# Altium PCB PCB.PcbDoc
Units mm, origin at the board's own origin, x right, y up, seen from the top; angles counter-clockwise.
Board outline 35 x 11 mm, 4 copper layers (TOP, GND, SIG, BOTTOM), stack 1.586 mm thick; 54 components, 35 nets, 188 pads, 91 vias.
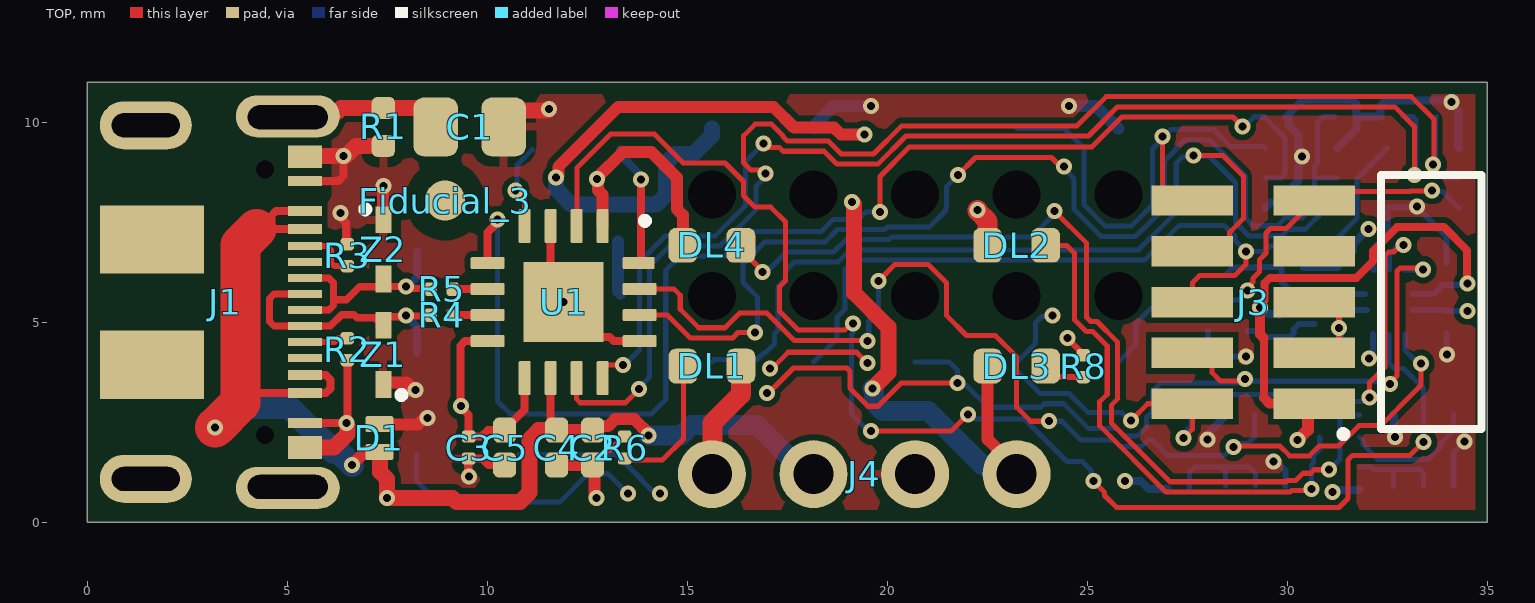
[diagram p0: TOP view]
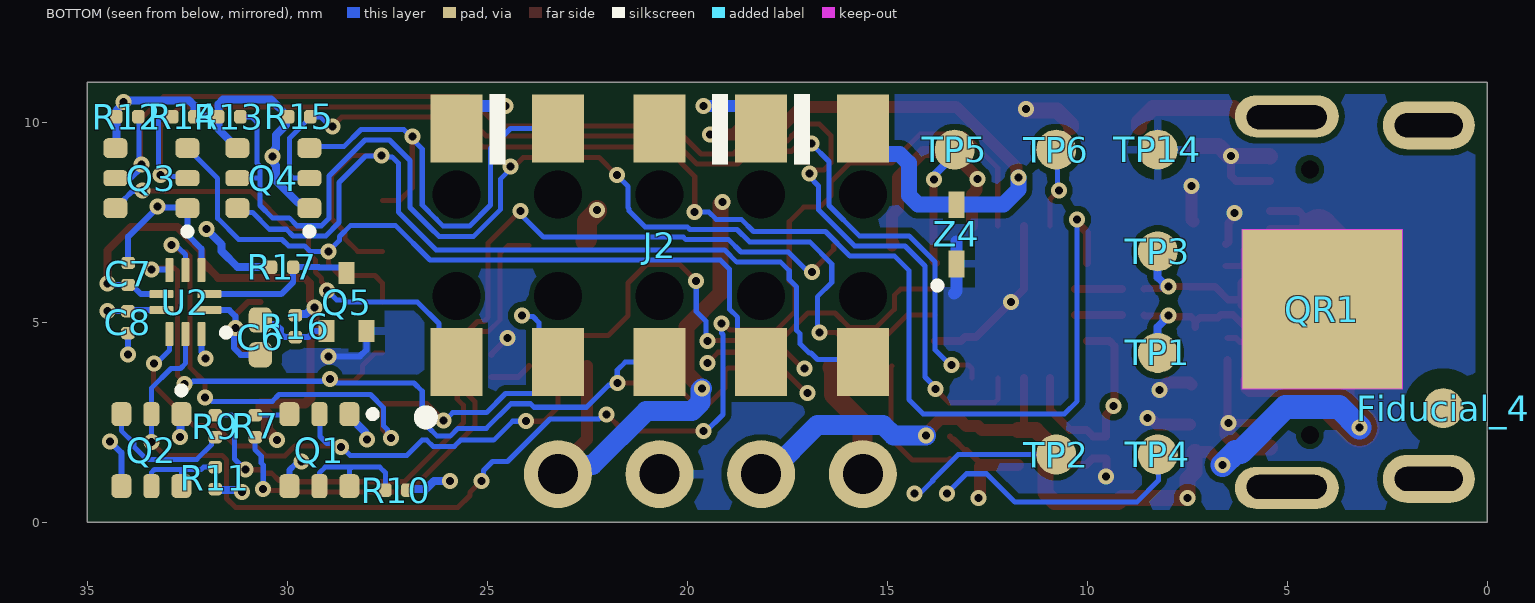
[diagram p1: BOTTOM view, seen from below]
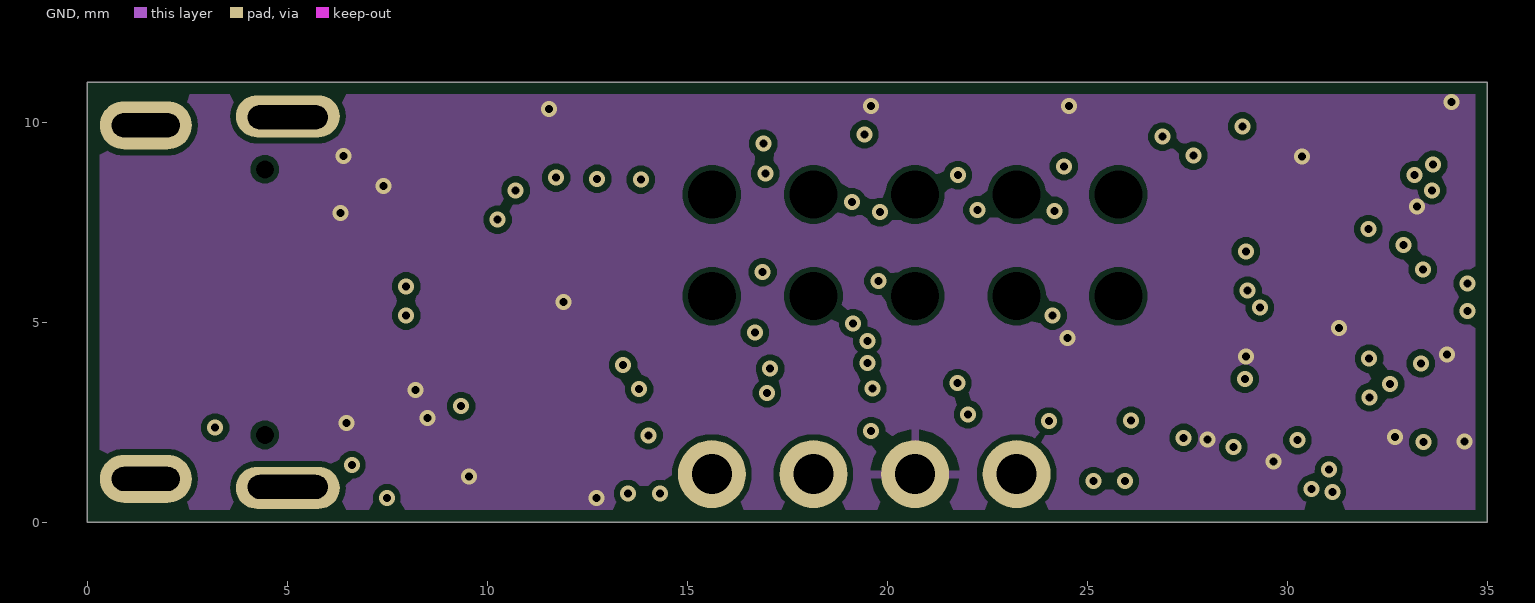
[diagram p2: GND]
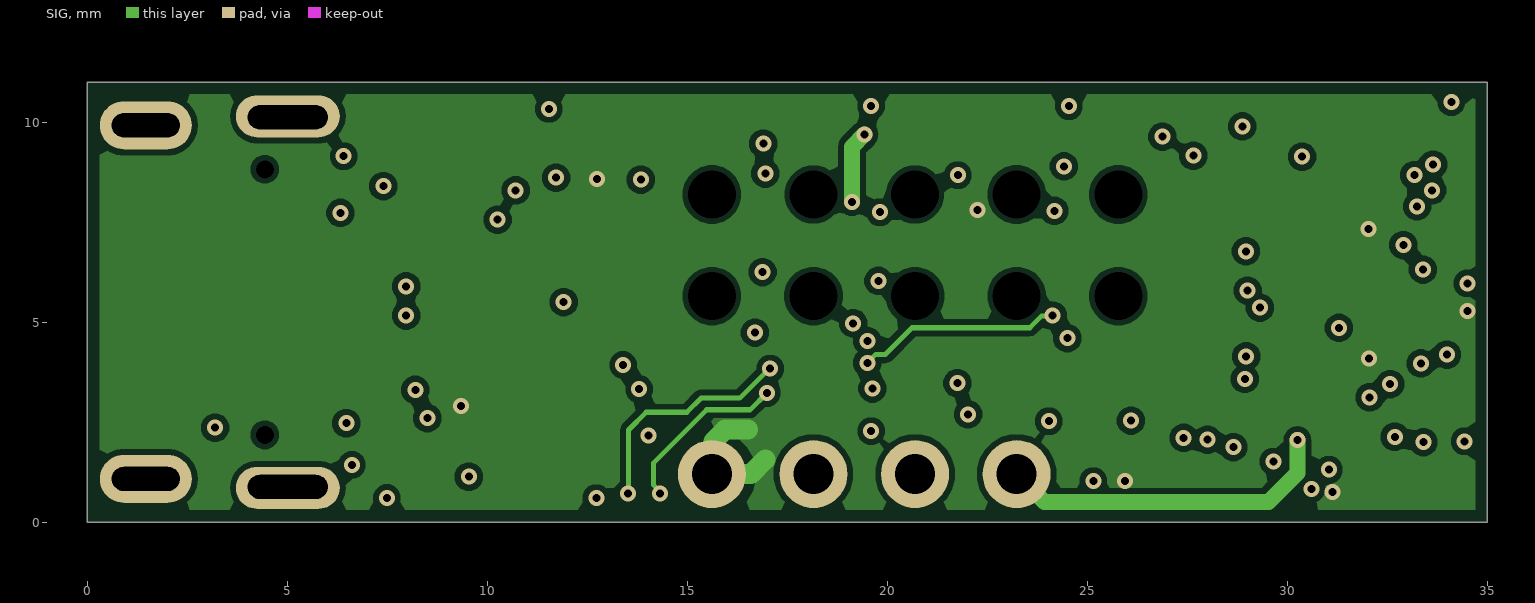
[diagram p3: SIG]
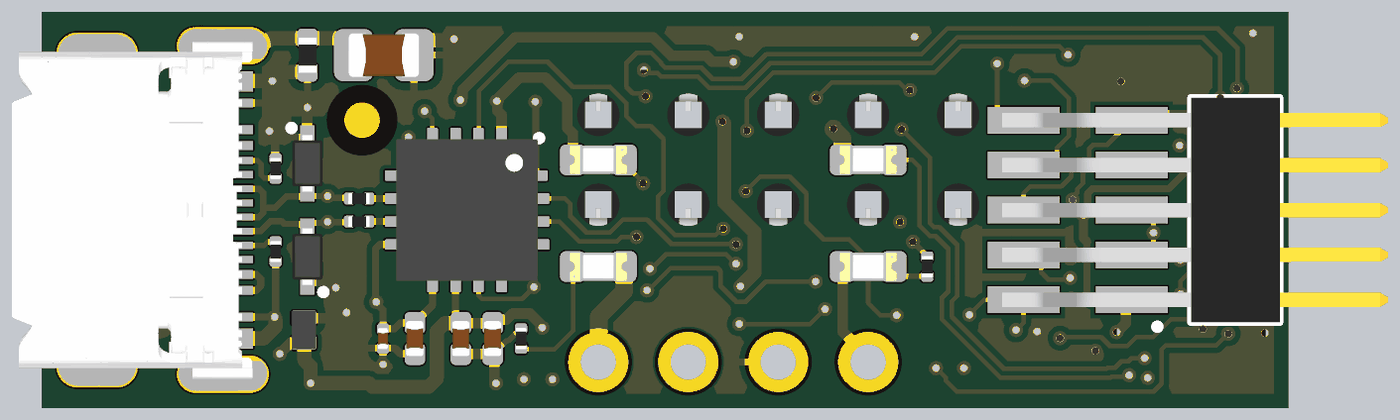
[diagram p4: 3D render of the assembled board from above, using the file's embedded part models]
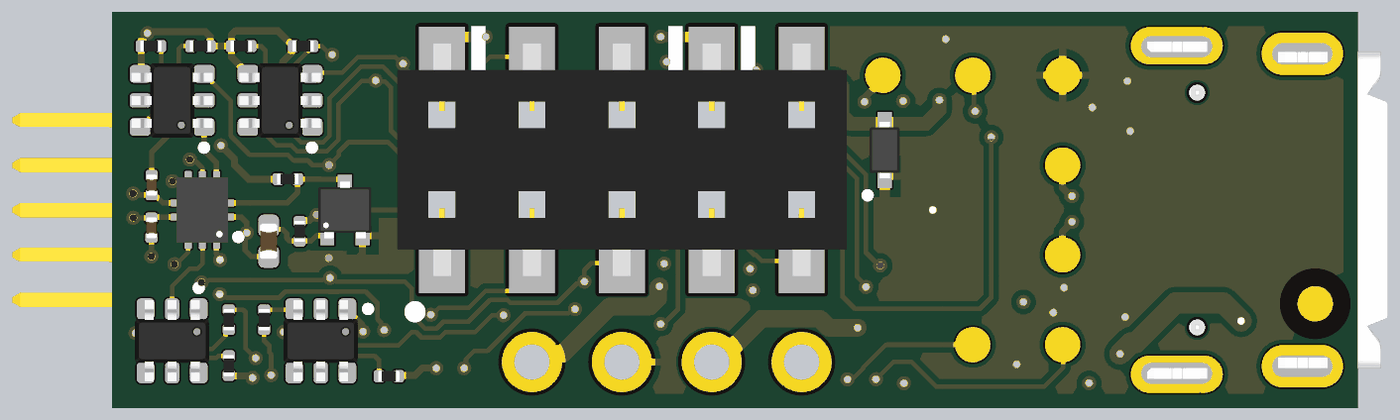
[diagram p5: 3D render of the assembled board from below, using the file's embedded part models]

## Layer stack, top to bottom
Top Solder: solder mask 0.0102, Solder Resist, Dk 3.5
TOP: signal copper 0.018
Dielectric 1: prepreg 0.14, PP-014, Dk 4.2
GND: signal copper 0.035
Dielectric2: core 1.2, FR-4, Dk 4.8
SIG: signal copper 0.035
Dielectric3: prepreg 0.14, PP-014, Dk 4.2
BOTTOM: signal copper 0.018
Bottom Solder: solder mask 0.0102, Solder Resist, Dk 3.5

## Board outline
0,0 35,0 35,11 0,11

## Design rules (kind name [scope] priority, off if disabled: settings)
BoardOutlineClearance Mousebites [(ObjectKind = 'Pad') And (Name = 'Free-MOUSEBITE')] p1: gap=0 ignorepadtopadclearanceinfootprint=FALSE
BoardOutlineClearance Silks [(OnLayer('Top Overlay') OR OnLayer('Bottom Overlay'))] p2: gap=0 ignorepadtopadclearanceinfootprint=FALSE
BoardOutlineClearance [All] p3: gap=0.3 ignorepadtopadclearanceinfootprint=FALSE
Clearance COPPER_0.15mm [All] p1: gap=0.127 ignorepadtopadclearanceinfootprint=FALSE except(0.15: Arc-Fill Arc-Poly Arc-Region Track-Fill Track-Poly Track-Region SMDPad-Fill SMDPad-Poly SMDPad-Region THPad-Fill THPad-Poly THPad-Region Via-Fill Via-Poly Via-Region Fill-Fill Fill-Poly Fill-Region Poly-Poly Poly-Region Region-Region)
Clearance "Generic clearance 0.127mm" [All] p2: gap=0.127 ignorepadtopadclearanceinfootprint=FALSE
ComponentClearance [All] p1: gap=0.2 collisioncheckmode=3 verticalgap=0 showdistances=TRUE
DiffPairsRouting USB [InDifferentialPairClass('USB')] p1: maxlimit=0.24 minlimit=0.127 mostfreqgap=0.24 toplayer_maxgap=0.127 toplayer_prefgap=0.127 toplayer_minwidth=0.18 toplayer_maxwidth=0.18 toplayer_prefwidth=0.18 midlayer2_mingap=0.24 midlayer2_minwidth=0.15 midlayer2_maxwidth=0.15 midlayer2_prefwidth=0.15 bottomlayer_maxgap=0.127 bottomlayer_prefgap=0.127 bottomlayer_minwidth=0.18 bottomlayer_maxwidth=0.18 bottomlayer_prefwidth=0.18 impedanceprofiledriven=TRUE impedanceprofileid={017A1981-E7F6-45B4-9447-017FE77E18B0} impedanceprofilevalue=90.000000 maxuncoupledlength=12.7
Height [All] p1: minheight=0 maxheight=30 prefheight=12.7
HoleSize [All] p1: absolutevalues=TRUE maxlimit=30 minlimit=0.1 maxpercent=80.000 minpercent=20.000
HoleToHoleClearance [All] p1: gap=0.25 allowstackedmicrovias=FALSE
MatchedLengths MatchedLengths_USB [InDifferentialPair('USB_D_1')] p1: tolerance=3.81 checknetsindiffpair=FALSE checkdiffpairvsdiffpair=TRUE checkxsignals=TRUE checkothers=TRUE
MinimumAnnularRing [All] p1: minimumring=0.09
PlaneConnect [All] p1: pad.planeconnectstyle=Relief pad.reliefexpansion=0.508 pad.reliefentries=4 pad.reliefconductorwidth=0.254 pad.reliefairgap=0.254 via.planeconnectstyle=Direct via.reliefexpansion=0.508 via.reliefentries=4 via.reliefconductorwidth=0.254 via.reliefairgap=0.254
PolygonConnect QR_polygon [(ObjectKind = 'Pad') And (Component = 'QR1') And (AsMM(PadXSize_AllLayers) = 4) And (AsMM(PadYSize_AllLayers) = 4)] p1: connectstyle=Direct reliefconductorwidth=0.254 reliefentries=4 polygonreliefangle="90 Angle" airgapwidth=0.254
PolygonConnect [All] p2: thpad.connectstyle=Relief thpad.reliefconductorwidth=0.2 thpad.reliefentries=4 thpad.polygonreliefangle="90 Angle" thpad.airgapwidth=0.254 smdpad.connectstyle=Relief smdpad.reliefconductorwidth=0.2 smdpad.reliefentries=4 smdpad.polygonreliefangle="90 Angle" smdpad.airgapwidth=0.254 via.connectstyle=Direct via.reliefconductorwidth=0.254 via.reliefentries=4 via.polygonreliefangle="90 Angle" via.airgapwidth=0.254
RoomDefinition TOP [InComponentClass('TOP')] p1: confinementstyle=ConfineIn formatcopy=TRUE lockcomponents=FALSE outline 77.708,-9.444 105.708,-9.444 105.708,-1.444 77.708,-1.444
RoutingVias StandardVias [All] p1: holewidth=0.2 width=0.4 viastyle="Through Hole" minholewidth=0.1 minwidth=0.2 maxholewidth=0.3 maxwidth=0.6
SMDToCorner [All] p1: distance=39370
SilkToSilkClearance [All] p1: silktosilkclearance=0.2
SilkToSolderMaskClearance [IsPad] p1: minsilkscreentomaskgap=0.15 clearancetoexposedcopper=TRUE
SolderMaskExpansion VIAtented [IsVia] p1: expansion=0.102 istentingtop=TRUE
SolderMaskExpansion [All] p2: expansion=0.05 istentingtop=FALSE
SupplyNets "Schematic Supply Nets_3" [InNet('+5V')] p1: voltage=0.000
SupplyNets "Schematic Supply Nets_2" [InNet('+3V3')] p2: voltage=0.000
SupplyNets "Schematic Supply Nets_1" [InNet('VTARGET')] p3: voltage=0.000
SupplyNets "Schematic Supply Nets" [InNet('GND')] p4: voltage=0.000
UnConnectedPin [All] p1:
UnRoutedNet [All] p1: checkbadconnections=TRUE
ViasUnderSMD [All] p1: allowed=FALSE
Width StandardTraces [All] p1: maxlimit=5 minlimit=0.127 preferedwidth=0.15 toplayer_prefwidth=0.127 bottomlayer_prefwidth=0.127 minimp=50.000000 maximp=50.000000 favimp=50.000000
21 further rules are at their usual default settings.

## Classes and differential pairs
differential pair class USB: USB_D_1
differential pair USB_D_1: +USB_D_1_P -USB_D_1_N

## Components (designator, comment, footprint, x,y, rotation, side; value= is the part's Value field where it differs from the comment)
C1 "FV21X472K102ECG" CAP-0805 9.558,9.88 r180 top value=4.7nF
C2 "C1005B103K500NT" CAP-0402 12.633,1.865 r90 top value=10nF
C3 "CL03A104KP3NNNC" CAP-0201 9.533,1.865 r90 top value=100nF
C4 "C1005A475M6R3NT" CAP-0402 11.733,1.865 r90 top value=4.7µF
C5 "C1005A475M6R3NT" CAP-0402 10.433,1.865 r90 top value=4.7µF
C6 "C1005A475M6R3NT" CAP-0402 30.675,4.618 r90 bottom value=4.7µF
C7 "CL03A104KP3NNNC" CAP-0201 33.979,6.204 r270 bottom value=100nF
C8 "CL03A104KP3NNNC" CAP-0201 33.985,5 r90 bottom value=100nF
D1 "STN101050B301" X1-DFN1006-2 7.3,2.1 r270 top
DL1 "LTST-C190KGKT" LEDC1608X80N-AK 15.614,3.9 r0 top
DL2 "LTST-C190KSKT" LEDC1608X80N-AK 23.234,6.92 r180 top
DL3 "XHY-STB0603SR" LEDC1608X80N-AK 23.234,3.9 r180 top
DL4 "LTST-C190KSKT" LEDC1608X80N-AK 15.614,6.92 r180 top
Fiducial_3 "Fiducial mark 1mm with 2mm solder" "Fiducial mark 1mm with circle-Footprint-1" 8.943,8.04 r90 top
Fiducial_4 "Fiducial mark 1mm with 2mm solder" "Fiducial mark 1mm with circle-Footprint-1" 1.1,2.848 r90 bottom
J1 "CX90B-16P" CX90B-16P-Footprint-1 3.45,5.5 r270 top locked
J2 "HLE-105-02-L-DV-K-TR" HLE-105-02-L-DV-BE-K-TR 20.694,6.92 r90 bottom locked
J3 "FTSH-105-01-L-DH-C-TR" FTSH-105-01-L-DH-C-TR 29.15,5.5 r270 top locked
J4 "HEADER TH 2.54mm VERT. 1x004POS" "PIN HEADER 2.54mm VERT. 1x4POS-Footprint-1" 19.424,1.2 r180 top locked
Q1 "2N7002DW-7-F" SOT363 29.2,1.8 r0 bottom
Q2 "2N7002DW-7-F" SOT363 33.4,1.8 r0 bottom
Q3 "2N7002DW-7-F" SOT363 33.4,8.6 r90 bottom
Q4 "2N7002DW-7-F" SOT363 30.35,8.6 r90 bottom
Q5 "PJE138K_R1_00001" SOT-523 28.52,5.5 r90 bottom
QR1 "QR CODE 4x4mm" "QR CODE 4x4mm" 4.129,5.324 r0 bottom
R1 "CRCW04021M00FKED" RES-0402 7.4,9.88 r90 top value=1M
R2 "RC0201FR-075K1L" RES-0201 6.5,4.325 r90 top value=5.1k
R3 "RC0201FR-075K1L" RES-0201 6.5,6.675 r270 top value=5.1k
R4 "CRCW020127R0FNED" RES-0201 8.858,5.175 r180 top value=27
R5 "CRCW020127R0FNED" RES-0201 8.858,5.825 r180 top value=27
R6 "RC0201FR-071KL" RES-0201 13.433,1.865 r270 top value=1k
R7 "AC0201FR-07330RL" RES-0201 30.8,2.4 r270 bottom value=330
R8 "AC0201FR-07330RL" RES-0201 24.9,3.9 r270 top value=330
R9 "AC0201FR-07330RL" RES-0201 31.8,2.4 r90 bottom value=330
R10 "RC0201FR-075K1L" RES-0201 27.275,0.8 r180 bottom value=5.1k
R11 "RC0201FR-075K1L" RES-0201 31.8,1.1 r270 bottom value=5.1k
R12 "RC0201FR-075K1L" RES-0201 34,10.135 r180 bottom value=5.1k
R13 "RC0201FR-075K1L" RES-0201 31.45,10.135 r180 bottom value=5.1k
R14 "RC0201FR-075K1L" RES-0201 32.6,10.135 r0 bottom value=5.1k
R15 "RC0201FR-075K1L" RES-0201 29.7,10.135 r180 bottom value=5.1k
R16 "RC0201FR-075K1L" RES-0201 29.798,4.898 r90 bottom value=5.1k
R17 "RC0201FR-075K1L" RES-0201 30.131,6.374 r180 bottom value=5.1k
TP1 "Test point 1.00mm" TP-1.00MM 8.238,4.23 r0 bottom
TP2 "Test point 1.00mm" TP-1.00MM 10.778,1.69 r90 bottom
TP3 "Test point 1.00mm" TP-1.00MM 8.238,6.77 r0 bottom
TP4 "Test point 1.00mm" TP-1.00MM 8.238,1.69 r90 bottom
TP5 "Test point 1.00mm" TP-1.00MM 13.318,9.31 r90 bottom
TP6 "Test point 1.00mm" TP-1.00MM 10.778,9.31 r90 bottom
TP14 "Test point 1.00mm" TP-1.00MM 8.238,9.31 r0 bottom
U1 "FT230XQ-R" "FTDI QFN16 4x4mm pitch 0.65mm" 11.908,5.5 r270 top
U2 "SN74AVC2T245RSWR" "TI RSW RSW0010A UFQN 10 1.4x1.8mm" 32.547,5.5 r0 bottom
Z1 "ESD321DYAR" ESD321DYAR 7.4,4.18 r270 top
Z2 "ESD321DYAR" ESD321DYAR 7.4,6.82 r90 top
Z4 "ESD321DYAR" ESD321DYAR 13.268,7.196 r270 bottom

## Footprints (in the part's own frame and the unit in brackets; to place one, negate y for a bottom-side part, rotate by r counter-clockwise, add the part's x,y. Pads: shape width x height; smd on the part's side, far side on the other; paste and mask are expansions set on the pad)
CAP-0201 [mm] "Chip Capacitor, 2-Leads, Body 0201 (in) 0603 (mm) IPC Medium Density"
  rrect52% 0.31x0.34 smd mask+0.05: 1(-0.275,0) 2(0.275,0)
  body extent -0.3,-0.15 0.3,0.15, height 0.3
CAP-0402 [mm] "Chip Capacitor, 2-Leads, Body  0402 (in) 1005 (mm), IPC Medium Density"
  rrect52% 0.63x0.58 smd mask+0.05: 1(-0.435,0) 2(0.435,0)
  body extent -0.5,-0.25 0.5,0.25, height 0.5
CAP-0805 [mm] "Chip Capacitor, Body 0805 imperial, 2.0x1.2mm, IPC Medium Density"
  rrect45% 1.11x1.47 smd mask+0.05: 1(-0.85,0) 2(0.85,0)
  body extent -1,-0.62 1,0.63, height 1.25
CX90B-16P-Footprint-1 [mm]
  rect 0.57x0.85 smd mask+0.05: A1(-3.635,1.988) A12(3.635,1.988)
  rect 0.25x0.85 smd mask+0.05: A4(-2.275,1.988) A9(2.275,1.988) B1(3.025,1.988) B4(1.825,1.988) B9(-1.825,1.988) B12(-3.025,1.988)
  rect 0.2x0.85 smd mask+0.05: A5(-1.4,1.988) A6(-0.6,1.988) A7(0.6,1.988) A8(1.4,1.988) B5(1,1.988) B6(0.2,1.988) B7(-0.2,1.988) B8(-1,1.988)
  round 0.2 hole 0.45 unplated paste-2539.97 mask+0.2: FIXING(-3.32,0.988) FIXING(3.32,0.988)
  rect 1.71x2.6 smd paste-0.3 mask+0.05: FIXING(-1.565,-1.837) FIXING(1.565,-1.837)
  oval 1.05x2.6 hole 0.6 slot 2 at 90 deg copper offset -0.025,0 mask+0.05: SHIELD1(-4.62,1.563)
  oval 1.05x2.6 hole 0.6 slot 2 at 90 deg copper offset 0.025,0 mask+0.05: SHIELD2(4.62,1.563)
  oval 1.2x2.3 hole 0.6 slot 1.7 at 90 deg mask+0.05: SHIELD3(-4.42,-1.987) SHIELD4(4.42,-1.987)
  body extent -4.77,-4.4 4.77,2.4, height 3.17
ESD321DYAR [mm] "ESD321DYAR SOD-523 1.6x0.8mm"
  rect 0.67x0.4 smd mask+0.05: 1(0.74,0) 2(-0.74,0)
  silkscreen extent 0.95,0.4 1.05,0.5, body extent -0.8,-0.43 0.8,0.43, height 0.82
"Fiducial mark 1mm with circle-Footprint-1" [mm]
  round 1 smd paste-10 mask+0.5: 1(0,0)
  TOP pour cut-out: 0,1 0.383,0.924 0.707,0.707 0.924,0.383 1,0 1,0 0.924,-0.383 0.707,-0.707 0.383,-0.924 0,-1 0,-1 -0.383,-0.924 -0.707,-0.707 -0.924,-0.383 -1,0 -1,0 -0.924,0.383 -0.707,0.707 -0.383,0.924 0,1
"FTDI QFN16 4x4mm pitch 0.65mm" [mm]
  rrect25% 0.85x0.3 smd mask+0.05: 1(-1.9,0.975) 2(-1.9,0.325) 3(-1.9,-0.325) 4(-1.9,-0.975) 9(1.9,-0.975) 10(1.9,-0.325) 11(1.9,0.325) 12(1.9,0.975)
  rrect25% 0.3x0.85 smd mask+0.05: 5(-0.975,-1.9) 6(-0.325,-1.9) 7(0.325,-1.9) 8(0.975,-1.9) 13(0.975,1.9) 14(0.325,1.9) 15(-0.325,1.9)
  rrect25% 0.3x0.8 smd mask+0.05: 16(-0.975,1.875)
  rect 2x2 smd paste-2539.97 mask+0.05: 17(0,0)
  silkscreen extent -2.08,1.98 -1.98,2.08, body extent -2,-2 2,2, height 0.8
FTSH-105-01-L-DH-C-TR [mm]
  rect 0.76x2.03 smd: 1(2.54,1.525) 2(2.54,-1.525) 3(1.27,1.525) 4(1.27,-1.525) 5(0,1.525) 6(0,-1.525) 7(-1.27,1.525) 8(-1.27,-1.525) 9(-2.54,1.525) 10(-2.54,-1.525)
  silkscreen extent -3.18,2.2 3.35,5.7, body extent -3.17,-2.13 3.18,8.76, height 3.43
HLE-105-02-L-DV-BE-K-TR [mm]
  rect 1.7x1.3 smd mask+0.1: 1(-2.92,5.08) 2(2.92,5.08) 3(-2.92,2.54) 4(2.92,2.54) 5(-2.92,0) 6(2.92,0) 7(-2.92,-2.54) 8(2.92,-2.54) 9(-2.92,-5.08) 10(2.92,-5.08)
  round 1 hole 1.2 unplated mask+0.1: HOLE(-1.27,-5.08) HOLE(-1.27,-2.54) HOLE(-1.27,2.54) HOLE(-1.27,5.08) HOLE(-1.27,0) HOLE(1.27,0) HOLE(1.27,-5.08) HOLE(1.27,-2.54) HOLE(1.27,2.54) HOLE(1.27,5.08)
  silkscreen extent -4.35,5.8 -4.25,5.9, body extent -3.29,-6.35 3.29,6.35, height 3.66
LEDC1608X80N-AK [mm]
  rrect50% 0.72x0.87 smd: A(0.725,0) C(-0.725,0)
  body extent -0.8,-0.4 0.8,0.4, height 0.79
"PIN HEADER 2.54mm VERT. 1x4POS-Footprint-1" [mm]
  round 1.7 hole 1 mask+0.1: 1(-3.81,0) 2(-1.27,0) 3(1.27,0) 4(3.81,0)
"QR CODE 4x4mm" [mm]
  rect 4x4 smd paste-2539.97 mask+0.1: PAD(0,0)
  TOP keep-out region: -2,2 2,2 2,-2 -2,-2
RES-0201 [mm] "Chip Resistor, 2-Leads, Body 0201 (in) 0603 (mm) IPC Medium Density"
  rrect52% 0.31x0.34 smd mask+0.05: 1(-0.275,0) 2(0.275,0)
  body extent -0.3,-0.15 0.3,0.15, height 0.24
RES-0402 [mm] "Chip Resistor, 2-Leads, Body  0402 (in) 1005 (mm), IPC Medium Density"
  rrect51% 0.55x0.58 smd mask+0.05: 1(-0.475,0) 2(0.475,0)
  body extent -0.5,-0.25 0.5,0.25, height 0.34
SOT363 [mm]
  rrect50% 0.5x0.6 smd mask+0.05: 1(-0.75,-0.9) 3(0.75,-0.9) 4(0.75,0.9) 6(-0.75,0.9)
  rrect50% 0.4x0.6 smd mask+0.05: 2(0,-0.9) 5(0,0.9)
  silkscreen extent -1.38,-0.95 -1.29,-0.85, body extent -1.05,-1.15 1.05,1.15, height 1
SOT-523 [mm] "SOTFL, 3-Leads, Body 1,50x1,60mm, Pitch 0,45mm, IPC Medium Density"
  rect 0.55x0.4 smd mask+0.05: 1(-0.725,0.5) 2(-0.725,-0.5) 3(0.725,0)
  body extent -0.8,-0.75 0.8,0.75, height 0.6
"TI RSW RSW0010A UFQN 10 1.4x1.8mm" [mm]
  rrect25% 0.7x0.2 smd mask+0.05: 1(-0.55,0.2)
  rrect25% 0.6x0.2 smd mask+0.05: 2(-0.6,-0.2) 6(0.6,-0.2) 7(0.6,0.2)
  rrect25% 0.2x0.6 smd mask+0.05: 3(-0.4,-0.8) 4(0,-0.8) 5(0.4,-0.8) 8(0.4,0.8) 9(0,0.8) 10(-0.4,0.8)
  silkscreen extent -1.07,0.71 -0.97,0.81, body extent -0.73,-0.93 0.73,0.93, height 0.55
TP-1.00MM [mm]
  rrect100% 1x1 smd paste-2.54: X(0,0)
X1-DFN1006-2 [mm] "DFN, 2-Leads, Body 0.61x1.01mm, Pitch 0.65mm, IPC High Density"
  rrect25% 0.4x0.7 smd mask+0.05: 1(-0.35,0) 2(0.35,0)
  body extent -0.54,-0.34 0.54,0.34, height 0.53

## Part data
C1: library part C0059-A.14, "CAP CHIP 0805 4.7nF 10% 1000V X7R", Case Code (Imperial)=0805, Dielectric=X7R, Manufacturer="PSA Shenzen", Manufacturer 2=KEMET, Part number 2=C0805V472KDRACTU, Part number 3=C0805C472KDRACTU, Tolerance=10%, Voltage=1kV
C2: library part C0009-A.15, "CAP CHIP 0402 10nF 10% 50V X7R", Case Code (Imperial)=0402, Dielectric=X7R, Manufacturer=Hottech, Manufacturer 2="Murata Electronics", Manufacturer 3=YAGEO, Part number 2=CC0402KRX7R9BB103, Tolerance=10%, Voltage=50V
C3 C7 C8: library part C0113-A.6, "CAP CHIP 0201 100nF 10% 10V X5R", Case Code (Imperial)=0201, Dielectric=X5R, Manufacturer="Samsung Electro-Mechanics", Tolerance=10%, Voltage=10V
C4 C5 C6: library part C0037-A.14, "CAP CHIP 0402 4.7uF 20% 6V3 X5R", Case Code (Imperial)=0402, Dielectric=X5R, Manufacturer=Hottech, Manufacturer 2="Samsung Electro-Mechanics", Manufacturer 3="Murata Electronics", Part number 2=CL05A475KQ5NRNC, Part number 3=GRM155R60J475ME47D, Tolerance=20%, Voltage=6.3V
D1: library part D0095-2, "TVS BIDIRECTIONAL SMD Vr = 5V, Vbr min =  5.5V, 300W, DFN1006-2", Manufacturer="Eaton Electronics", Power max=300W
DL1: library part L0009-A.6, "LED SMD 0603 GREEN/568 15mcd 120^", Manufacturer=Liteon
DL2 DL4: library part L0008-A.6, "LED SMD 0603 GIA588   8mcd 120^", Manufacturer=Liteon
DL3: library part L0024-A.4, "LED SMD 0603 RED 625nm, water clear, 42 to 88 mcd, 120 degrees, 1.6x0.8x0.6mm", Manufacturer="Shenzen Corehy Technology"
Fiducial_3 Fiducial_4: library part UT0024-A.6
J1: library part J0272-A.3, "CONN RCPT USB3.1 TYPEC 16POS SMD", Manufacturer=Hirose
J2: library part J0491-A.6, "CONN HEADER FEMALE SMD 2.54mm 2x5POS DUAL ROW Top Entry heigth 3.66mm", Manufacturer=Samtec
J3: library part J0493-A.4, "CONN HEADER FEMALE SMD 1.27mm 2x5POS HORIZONTAL DUAL ROW heigth 3.66mm", Manufacturer=Samtec
J4: library part J0162-A.6
Q1 Q2 Q3 Q4: library part T0011-A.12, "MOSFET 2N-CH 60V 0.32A SOT363", Manufacturer="Diodes Inc.", Manufacturer 2=Nexperia, Manufacturer Part Number 2=2N7002PS,115
Q5: library part T0062-A.2, "MOSFET N-CH, 50V, ID 0.35A, Vth max 1.5V, SOT-523", Manufacturer=Panjit
QR1: library part QR-0001-A.5, "QR CODE 4x4mm on layer 34 (This is not a component)", Manufacturer="This is not a component"
R1: library part R0058-A.24, "RES CHIP 0402 1M 1% 1/16W", Case Code (Imperial)=0402, Manufacturer=Vishay, Power=62.5mW, Temperature coefficient=100ppm, Tolerance=1%
R2 R3 R10 R11 R12 R13 R14 R15 R16 R17: library part R0169-A.25, "RES CHIP 0201 5k1 1% 1/20W", Case Code (Imperial)=0201, Manufacturer=Yageo, Manufacturer 2=Panasonic, Part number 2=ERJ-1GNF5101C, Power=50mW, Temperature coefficient=200ppm, Tolerance=1%
R4 R5: library part R0197-A.20, "RES CHIP 0201 27R 1% 1/20W", Case Code (Imperial)=0201, Manufacturer=Vishay, Power=50mW, Temperature coefficient=200ppm, Tolerance=1%
R6: library part R0195-A.22, "RES CHIP 0201 1k 1% 1/20W", Case Code (Imperial)=0201, Manufacturer=Yageo, Power=50mW, Temperature coefficient=200ppm, Tolerance=1%
R7 R8 R9: library part R0149-A.21, "RES CHIP 0201 330R 1% 1/20W", Case Code (Imperial)=0201, Manufacturer=Yageo, Manufacturer 2="Samsung Electro-Mechanics", Power=50mW, Temperature coefficient=200ppm, Tolerance=1%
TP1 TP2 TP3 TP4 TP5 TP6 TP14: library part UT0013-A.6, Manufacturer="This is not a component"
U1: library part U0428-A.3, "IC FTDI USB to BASIC UART, +5V single supply, x4 IO, VCCIO 1V8 to 3V3, 3V3OUT internal LDO, QFN16 4x4mm", Manufacturer=FTDI
U2: library part U0430-A.2, "IC TRANSLATOR LEVEL SHIFTER Unidirectional, 2BIT, VCCA and VCCB from 1.2V to 3.6V, Output enable, indipendent DIR pins, UQFN10 1.8x1.4mm", Manufacturer="Texas Instruments"
Z1 Z2 Z4: library part P0022-5, "TVS 1CH, 30kV, USB 2.0 ETH 10/100/1000, 0-3.6V, 0.9pF, IEC61000-4-5 peak current 80A surge 40W 6A, DC breakdown min 4.5V, SOD523 1.6x0.8mm", Manufacturer="Texas Instruments"

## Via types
v1: diameter 0.4, hole 0.2, TOP to BOTTOM, tented both sides, 91 vias

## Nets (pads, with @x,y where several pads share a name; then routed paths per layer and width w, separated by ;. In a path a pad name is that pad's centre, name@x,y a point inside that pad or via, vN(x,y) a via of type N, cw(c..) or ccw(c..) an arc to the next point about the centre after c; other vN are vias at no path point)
+3V3: C3.2 C5.2 C8.2 DL1.A DL2.A DL4.A J4.4 R10.2 R11.2 R17.1 U1.1 U1.8 U1.9 U2.7 U2.10 | length 24.2
  TOP w0.2: v1(9.344,2.899) 9.326,2.917 9.326,4.408 9.444,4.525 U1.8 ; v1@9.355,2.911 9.355,2.86 9.533,2.682 C3.2 9.854,2.14 10.022,2.307 C5.2@10.426,2.307 ; C5.2@10.283,2.3 C5.2 ; C5.2@10.433,2.308 10.933,2.808 U1.9
  TOP w0.3: v1@12.736,8.591 12.736,8.603 13.381,9.249 14.105,9.249 14.737,8.617 14.737,7.827 14.889,7.675 DL4.A DL4.A@14.841,6.968 ; v1(12.745,8.581) 12.764,8.562 12.764,8.304 12.883,8.186 U1.1
  TOP w0.5: J4.4@15.639,1.5 15.626,1.513 15.626,2.478 16.339,3.191 16.339,3.843 DL1.A@16.367,3.872 ; v1(22.252,7.803) 22.252,7.776 22.509,7.519 22.509,7.066 DL2.A@22.545,7.03
  SIG w0.5: 16.518,2.31 15.943,2.31 15.65,2.017 15.65,1.236 J4.4 16.586,1.2 16.955,1.569
  BOTTOM w0.15: R10.2 R10.2@27,0.825 ; v1(32.047,4.088) 32.047,4.156 32.147,4.256 U2.10 ; U2.7 33.96,5.3 C8.2 34.495,5.275 v1(34.5,5.28)
  BOTTOM w0.2: v1(25.936,1.027) 26.334,1.027 26.536,0.825 R10.2@27,0.825 ; R17.1 31.242,6.374 31.644,6.776 31.644,6.946 v1(32.025,7.326) ; v1(31.128,0.754) 31.182,0.754 31.236,0.808 31.783,0.808 R11.2
+5V: C2.2 C4.2 D1.2 J1.A4 J1.A9 J1.B4 J1.B9 J4.3 U1.10 | length 32
  TOP w0.2: 3.826,2.991 4.06,3.225 J1.A9 5.963,3.225 6.08,3.342 6.08,3.558 5.963,3.675 J1.B4 ; 4.225,7.325 4.6,7.325 ; J1.B9 4.6,7.325 ; J1.A4 4.717,7.775 4.6,7.658 4.6,7.325 ; C4.2@11.583,2.3 U1.10
  TOP w0.3: v1(6.617,1.43) 6.936,1.749 D1.2 ; C4.2 C2.2 12.733,2.4 13.023,2.4 13.195,2.572 13.674,2.572 14.03,2.216 v1(14.03,2.169)
  TOP w0.4: D1.2 7.317,1.75 7.317,1.254 7.49,1.081 v1(7.49,0.605) 9.128,0.605 9.232,0.5 10.816,0.5 11.05,0.734 11.05,2.066 11.284,2.3 C4.2
  TOP w1: v1(3.195,2.36) 3.826,2.991 3.826,6.926 4.225,7.325
  BOTTOM w0.5: v1(14.03,2.169) 14.848,2.169 15.106,2.427 16.748,2.427 17.975,1.2 J4.3@18.3,1.2
  BOTTOM w0.6: v1(3.195,2.36) 3.709,2.874 5.046,2.874 6.173,1.747 6.3,1.747 v1(6.617,1.43)
CBUS0_1: Q3.2 R14.2 U1.12 | length 29.5
  TOP w0.127: U1.12 12.883,3.84 12.97,3.926 13.39,3.926 v1(13.393,3.929) ; v1(16.899,9.459) 16.989,9.369 17.298,9.369 17.394,9.273 18.419,9.273 18.744,8.948 19.76,8.948 20.466,9.653 25.028,9.653 25.757,10.383 32.683,10.383 33.176,9.889 v1(33.176,8.673)
  BOTTOM w0.127: v1(13.393,3.929) 13.428,3.929 13.804,4.305 13.804,6.506 14.456,7.158 15.699,7.158 16.458,7.916 16.458,9.018 v1(16.899,9.459) ; Q3.2 32.537,8.636 33.14,8.636 v1(33.176,8.673) ; R14.2@32.88,10.14 33.13,10.14 33.22,10.05 33.22,8.686 v1@33.182,8.648
CBUS0_OPENDRAIN_1: J2.1 J3.9 Q3.6 | length 11.4
  TOP w0.127: v1(29.006,5.79) 29.006,5.864 29.142,6.001 29.142,6.094 29.299,6.251 29.299,6.552 29.469,6.722 29.469,7.229 29.581,7.341 29.975,7.341 30.898,8.263 33.061,8.263 33.081,8.282 33.606,8.282 v1(33.619,8.295)
  BOTTOM w0.127: J2.1 26.211,4.437 26.211,4.966 26.745,5.5 28.54,5.5 28.597,5.557 28.773,5.557 v1(29.006,5.79) ; v1(33.619,8.295) 33.65,8.264 33.886,8.264 34.063,8.086 34.063,8.07 34.283,7.85 Q3.6
CBUS1_1: Q3.5 R12.2 U1.11 | length 32.8
  TOP w0.127: U1.11 12.233,3.075 12.324,2.984 13.456,2.984 v1(13.795,3.323) ; v1(16.948,8.715) 16.858,8.806 16.585,8.806 16.407,8.984 16.407,9.638 16.408,9.639 16.408,9.662 16.696,9.95 17.102,9.95 17.389,9.662 17.389,9.637 17.5,9.527 18.524,9.527 18.849,9.202 19.655,9.202 20.361,9.907 24.745,9.907 25.474,10.637 33.101,10.637 33.666,10.071 33.666,8.96 v1(33.647,8.94)
  BOTTOM w0.127: v1(13.795,3.323) 13.795,3.363 14.058,3.626 14.058,6.4 14.561,6.904 15.817,6.904 16.721,7.807 16.721,8.404 16.948,8.631 v1(16.948,8.715) ; R12.2 33.705,10.115 33.705,9.073 33.647,9.014 33.647,8.853 33.9,8.6 Q3.5
CBUS1_OPENDRAIN_1: J2.7 J3.6 Q3.3 | length 21
  TOP w0.127: J3.6 27.625,5.98 27.81,6.165 28.684,6.165 28.967,6.448 v1(28.967,6.772)
  BOTTOM w0.127: J2.7 18.74,4.586 18.74,5.119 18.944,5.323 18.944,6.321 19.176,6.553 26.434,6.553 27.3,7.419 28.417,7.419 28.694,7.141 28.694,7.044 v1(28.967,6.772) ; v1@28.989,6.765 29.43,6.765 29.566,6.901 29.966,6.901 30.133,7.068 31.214,7.068 31.74,7.594 31.74,8.59 Q3.3
CBUS2_1: Q4.2 R15.2 U1.5 | length 32.9
  TOP w0.127: v1(19.814,7.749) 19.814,8.643 20.554,9.383 25.117,9.383 25.862,10.129 28.64,10.129 v1(28.876,9.892)
  TOP w0.2: U1.5 10.008,7.242 10.255,7.489 v1(10.255,7.561)
  BOTTOM w0.127: v1(10.255,7.561) 10.255,3.023 10.571,2.707 14.105,2.707 14.462,3.063 14.462,6.295 14.816,6.65 15.931,6.65 16.548,7.266 18.348,7.266 18.651,7.569 19.278,7.569 19.458,7.749 v1(19.814,7.749) ; v1(28.876,9.892) 28.927,9.892 29.17,10.135 R15.2 29.425,10.121 29.941,9.606 29.941,8.691 29.85,8.6 Q4.2
CBUS2_OPENDRAIN_1: J2.9 J3.8 Q4.6 | length 25.3
  TOP w0.127: J3.8 28.241,6.77 28.558,7.087 28.558,7.248 28.901,7.591 28.901,8.653 28.394,9.16 v1(27.65,9.16)
  BOTTOM w0.127: J2.9 15.677,4.063 16.745,4.063 16.909,4.227 16.949,4.227 17.181,4.46 17.181,4.712 17.267,4.797 17.267,5.881 17.453,6.066 17.453,6.284 17.667,6.498 18.762,6.498 19.071,6.807 26.281,6.807 27.223,7.748 27.223,8.974 27.38,9.131 27.621,9.131 v1(27.65,9.16) 27.658,9.152 28.043,9.152 28.706,8.49 28.706,7.489 29.039,7.155 29.861,7.155 30.028,7.322 30.449,7.322 30.867,7.741 31.14,7.741 Q4.6
CBUS3_1: Q4.5 R13.2 U1.14 | length 28.7
  TOP w0.127: U1.14 14.506,5.175 15.076,4.605 16.137,4.605 16.269,4.738 v1(16.691,4.738) ; v1(21.763,8.673) 22.203,9.114 24.105,9.114 24.326,8.892 v1(24.416,8.892)
  BOTTOM w0.127: v1(16.691,4.738) 16.75,4.796 16.75,5.632 16.389,5.993 16.389,6.455 16.94,7.006 18.447,7.006 18.756,7.315 19.933,7.315 20.001,7.383 21.057,7.383 21.454,7.779 21.454,7.832 21.484,7.863 21.484,8.395 v1(21.763,8.673) ; v1(24.416,8.892) 24.416,8.832 24.666,8.581 24.666,7.82 25.341,7.145 26.207,7.145 26.326,7.265 26.333,7.265 26.933,7.865 26.933,9.043 27.445,9.555 28.06,9.555 28.96,8.656 28.96,7.594 29.144,7.409 29.756,7.409 29.953,7.607 30.374,7.607 30.682,7.915 30.682,8.6 ; R13.2 30.894,10.135 30.759,10 30.759,8.974 30.682,8.897 30.682,8.6 ; Q4.5 30.682,8.6
CBUS3_OPENDRAIN_1: J2.4 J3.10 Q4.3 | length 12.3
  TOP w0.127: v1(26.876,9.638) 26.876,8.357 27.193,8.04 J3.10
  BOTTOM w0.127: J2.4 24.42,9.84 24.92,9.339 24.92,7.926 25.447,7.399 26.101,7.399 26.276,7.574 26.628,7.926 26.628,9.327 26.895,9.594 26.895,9.625 27.087,9.818 28.157,9.818 28.589,9.386 29.414,9.386 Q4.3
CC1_1: J1.A5 R3.2 | length 1.5
  TOP w0.15: J1.A5 5.989,6.9 6.092,6.797 6.092,6.488 6.18,6.4 R3.2@6.55,6.4
CC2_1: J1.B5 R2.2 | length 1.1
  TOP w0.15: J1.B5 6.177,4.5 6.277,4.6 R2.2
GND: C1.1 C2.1 C3.1 C4.1 C5.1 C6.1 C7.1 C8.1 D1.1 J1.A1 J1.A12 J1.B1 J1.B12 J2.2 J2.8 J3.3 J3.5 J4.2 Q1.1 Q1.4 Q2.1 Q2.4 Q3.1 Q3.4 Q4.1 Q4.4 Q5.2 QR1.PAD R1.1 R2.1 R3.1 R6.1 R8.1 R12.1 R13.1 R14.1 R15.1 TP14.X U1.3 U1.13 U1.17 U2.1 U2.3 Z1.1 Z2.1 Z4.1 | length 50.9
  TOP w0.15: C2.1@12.642,1.43 13.015,1.803 13.07,1.803 13.331,2.063 13.356,2.063 R6.1 ; v1(24.5,4.6) 24.9,4.2 R8.1 ; J3.3 30.985,4.23 31.29,4.535 31.29,5.195 30.985,5.5 J3.5
  TOP w0.2: J1.B1 v1@6.475,2.475 ; J1.B12 6.277,8.525 6.41,8.658 v1(6.41,9.149) ; v1(6.327,7.729) 6.327,7.621 6.473,7.475 6.473,7.005 R3.1@6.528,6.95 ; v1(6.474,2.474) v1@6.475,2.475 ; R2.1 6.5,2.5 v1@6.475,2.475 ; v1@6.575,2.475 v1@6.475,2.475 ; v1(9.537,1.135) 9.519,1.153 9.519,1.576 C3.1 9.871,1.59 10.031,1.43 C5.1 ; U1.3 11.583,5.825 v1(11.908,5.5) 12.782,4.626 13.058,4.626 13.159,4.525 U1.13
  TOP w0.3: Z2.1@7.35,7.51 7.393,7.553 7.393,8.393 v1(7.4,8.4) ; Z1.1@7.4,3.441 7.45,3.491 7.984,3.491 8.171,3.304 v1(8.198,3.304) ; D1.1@7.437,2.442 8.261,2.442 8.419,2.6 v1(8.5,2.6) ; C4.1 C2.1 12.678,1.385 12.678,0.645 v1(12.724,0.6)
  TOP w0.4: J1.A12 6.165,1.865 6.5,2.2 v1@6.5,2.4 ; J1.A1 5.451,9.149 v1(6.41,9.149) 6.463,9.149 6.719,9.405 R1.1 ; C1.1 10.408,9.943 10.759,10.295 11.5,10.295 v1(11.538,10.333)
  BOTTOM w0.15: Q5.2 28.02,4.308 28.185,4.143 v1(28.973,4.143) ; v1(29.649,1.514) 29.697,1.466 29.784,1.466 29.95,1.3 Q1.4 ; C6.1 31.166,4.183 31.337,4.355 31.337,4.741 31.287,4.791 31.225,4.791 v1(31.29,4.856) 31.298,4.863 31.298,5.15 31.448,5.3 U2.1 ; U2.3@32.148,6.301 32.148,6.838 32.5,7.19 Q3.1 32.512,7.861 33.231,7.861 v1@33.242,7.873 ; v1(33.242,7.892) 33.242,7.874 33.979,7.136 C7.1 ; C8.1 33.985,4.188 v1(33.987,4.186) ; Q2.4 34.15,1.735 v1(34.435,2.02)
  BOTTOM w0.2: v1(28.005,2.061) 28.043,2.1 28.043,2.243 28.45,2.65 Q1.1 ; Q4.1 29.585,7.985 29.735,7.985 30.282,8.532 30.282,8.919 30.331,8.967 30.331,9.097 v1(30.369,9.136) 30.331,9.174 30.331,9.304 30.282,9.353 30.282,9.675 30.03,9.927 30.03,10.08 R15.1 30.405,10.565 31.608,10.565 31.725,10.448 R13.1 ; Q4.4 31.725,9.825 R13.1 ; Q2.1 32.668,2.682 32.668,2.151 v1(32.686,2.133) ; v1(34.1,10.5) 34.046,10.5 34,10.546 32.459,10.546 32.325,10.412 R14.1 R13.1 ; v1@34.11,10.456 34.275,10.29 34.275,9.375 Q3.4
  BOTTOM w0.3: 13.268,7.01 Z4.1 13.268,5.773 13.331,5.71 ; J2.8 18.154,9.9 18.654,10.4 v1(19.595,10.4) ; v1(24.542,10.398) 25.216,10.398 J2.2
NetC6_2: C6.2 Q5.1 R16.1 | length 1.9
  BOTTOM w0.15: Q5.1 29.32,4.775 29.473,4.623 R16.1 30.068,4.623 30.16,4.715 30.16,4.829 30.285,4.953 C6.2@30.675,4.953
NetDL1_C: DL1.C R6.2 | length 3.5
  TOP w0.127: R6.2 13.471,1.552 14.375,1.552 14.903,2.079 14.903,3.886 DL1.C
NetDL2_C: DL2.C R7.2 | length 13
  TOP w0.127: DL2.C 24.48,6.92 24.678,6.721 24.678,5.06 24.976,4.763 25.137,4.763 25.497,4.403 25.497,3.197 25.309,3.009 25.309,2.409 26.964,0.754 30.072,0.754 30.104,0.786 30.56,0.786 v1(30.603,0.829)
  BOTTOM w0.127: v1(30.603,0.829) 30.603,1.424 30.651,1.473 30.651,1.655 30.812,1.816 30.812,2.113 R7.2
NetDL3_C: DL3.C R8.2 | length 1.1
  TOP w0.15: DL3.C 24.234,3.625 R8.2
NetDL4_C: DL4.C R9.2 | length 23.1
  TOP w0.127: DL4.C 16.339,6.819 16.88,6.278 v1(16.88,6.252) ; v1(24.176,7.781) 24.983,6.973 24.983,5.118 25.085,5.017 25.243,5.017 25.751,4.508 25.751,3.074 25.6,2.923 25.6,2.477 27.069,1.008 29.967,1.008 29.998,1.04 30.208,1.04 30.391,1.223 30.587,1.223 30.674,1.31 v1(31.041,1.31)
  BOTTOM w0.127: v1(16.88,6.252) 16.977,6.252 17.478,6.752 18.657,6.752 18.966,7.061 20.038,7.061 20.1,7.123 23.596,7.123 24.176,7.703 v1(24.176,7.781) ; v1(31.041,1.31) 31.052,1.31 31.318,1.576 31.318,2.601 31.392,2.675 R9.2
NetQ1_3: Q1.3 R7.1 | length 0.9
  BOTTOM w0.127: Q1.3 29.975,2.675 R7.1
NetQ1_5: Q1.5 Q1.6 R10.1 | length 3
  BOTTOM w0.127: R10.1@27.55,0.8 27.55,1.239 27.686,1.375 28.045,1.375 28.386,1.375 ; Q1.6 28.45,1.31 28.386,1.375 ; Q1.5 29.2,1.228 29.053,1.375 28.386,1.375
NetQ2_3: Q2.3 R9.1 | length 3.4
  BOTTOM w0.127: R9.1 31.806,2.125 31.896,2.035 31.896,1.934 32.261,1.569 33.521,1.569 33.836,1.883 33.836,1.973 34.15,2.287 Q2.3
NetQ2_5: Q2.5 Q2.6 R11.1 | length 2.4
  BOTTOM w0.127: R11.1 32.096,1.375 32.156,1.315 33.321,1.315 33.4,1.236 Q2.5 ; Q2.6 32.65,1.277
NetQ5_3: Q5.3 R17.2 U2.2 | length 4
  BOTTOM w0.15: Q5.3 28.52,6.245 28.645,6.37 29.209,6.37 29.213,6.374 R17.2 29.856,5.996 30.153,5.7 U2.2
NetR4_1: R4.1 U1.7 | length 1.2
  TOP w0.2: R4.1 U1.7 U1.7@10.308,5.175
NetR5_1: R5.1 U1.6 | length 1.2
  TOP w0.2: R5.1 U1.6 U1.6@10.308,5.825
NetTP5_X: TP5.X U1.16 | length 3.1
  TOP w0.2: U1.16 13.795,6.475 13.845,6.525 v1@13.845,8.554
  BOTTOM w0.2: TP5.X 13.318,9.189 13.836,8.671 v1(13.836,8.563)
NetTP6_X: TP6.X U1.4 | length 2.2
  TOP w0.127: v1@10.715,8.293 v1(10.711,8.293) 10.933,8.071 U1.4
  BOTTOM w0.127: v1(10.711,8.293) 10.744,8.327 10.744,8.93 TP6.X@11.124,9.31
RXD_1: Q2.2 U1.2 U2.9 | length 35
  TOP w0.127: U1.2@12.239,7.406 12.239,8.856 13.084,9.701 14.176,9.701 14.897,8.98 15.941,8.98 16.404,8.517 16.404,8.162 16.692,7.875 17.088,7.875 17.453,7.511 17.453,6.034 17.304,5.885 17.304,5.272 17.777,4.798 18.934,4.798 19.105,4.97 v1(19.144,4.97) ; v1(19.595,2.276) 21.597,2.276 v1(22.017,2.696) ; v1(25.149,1.027) 25.432,0.744 25.432,0.668 25.737,0.363 31.29,0.363 31.519,0.592 31.519,1.558 31.63,1.67 33.07,1.67 v1(33.4,2)
  BOTTOM w0.127: v1(19.144,4.97) 19.144,4.726 19.108,4.69 19.108,2.692 19.524,2.276 v1(19.595,2.276) ; v1(22.017,2.696) 22.091,2.696 22.211,2.576 23.432,2.576 24.493,1.515 24.872,1.515 25.097,1.29 25.097,1.079 v1(25.149,1.027) ; U2.9@32.541,4.694 32.541,3.974 32.673,3.842 32.905,3.842 33.4,3.347 Q2.2 v1(33.4,2)
RXD_VTARGET_1: J2.3 J3.2 TP4.X U2.4 | length 38.8
  TOP w0.127: v1(17.071,3.837) 17.111,3.837 17.521,4.247 19.228,4.247 19.495,3.98 v1(19.499,3.98) ; v1(26.091,2.539) 26.091,2.541 26.51,2.96 J3.2 27.625,2.32 v1(27.41,2.105) ; v1(32.058,3.12) 32.058,3.492 32.438,3.871 32.438,6.658 32.528,6.748 32.654,6.748 32.833,6.927 v1(32.9,6.927)
  SIG w0.127: v1(13.511,0.714) 13.532,0.734 13.532,2.305 13.973,2.746 14.988,2.746 15.342,3.1 16.309,3.1 17.046,3.837 v1(17.071,3.837) ; v1(19.499,3.98) 19.713,4.194 19.952,4.194 20.617,4.859 23.561,4.859 23.851,5.149 24.117,5.149 v1(24.133,5.165)
  BOTTOM w0.127: TP4.X 8.225,1.677 8.225,1.04 8.765,0.5 11.808,0.5 12.518,1.21 13.018,1.21 13.511,0.717 v1(13.511,0.714) ; v1(24.133,5.165) 24.107,5.139 23.858,5.139 23.705,4.987 23.705,4.471 J2.3 23.234,3.8 23.82,3.213 24.545,3.213 25.023,2.735 25.863,2.735 26.06,2.539 v1(26.091,2.539) ; v1(27.41,2.105) 27.41,2.179 27.499,2.268 27.499,2.315 27.594,2.409 27.594,2.862 27.923,3.19 28.706,3.19 28.708,3.188 28.977,3.188 28.98,3.19 30.206,3.19 30.376,3.021 31.885,3.021 31.985,3.12 v1(32.058,3.12) ; U2.4@32.548,6.301 32.548,6.692 32.731,6.875 32.848,6.875 v1(32.9,6.927)
TXD_1: Q1.2 U1.15 U2.8 | length 29
  TOP w0.127: U1.15 14.671,5.825 14.823,5.673 14.823,5.323 15.287,4.859 15.941,4.859 16.31,5.228 16.988,5.228 17.679,4.537 19.49,4.537 v1(19.499,4.528) ; v1(19.777,6.03) 20.188,6.44 21.021,6.44 21.484,5.977 21.484,5.162 21.978,4.668 22.7,4.668 23.234,4.134 23.234,2.872 23.583,2.522 v1(24.037,2.523) ; v1(28.652,1.876) 28.681,1.904 29.811,1.904 30.059,1.657 30.547,1.657 30.795,1.904 31.284,1.904 31.791,2.411 32.336,2.411 33.194,3.269 33.194,3.271 33.342,3.419 33.342,3.961 v1(33.337,3.966)
  BOTTOM w0.127: v1(19.499,4.528) 19.535,4.564 19.535,5.025 19.777,5.267 v1(19.777,6.03) ; v1(24.037,2.523) 24.367,2.523 24.841,2.049 25.67,2.049 25.824,1.894 26.358,1.894 26.512,2.049 26.633,2.049 27.011,1.671 28.433,1.671 28.638,1.876 v1(28.652,1.876) 28.743,1.966 29.01,1.966 29.184,2.14 29.184,2.684 Q1.2 ; U2.8@32.945,4.698 32.945,4.3 33.279,3.966 v1(33.337,3.966)
TXD_VTARGET_1: J2.5 J3.4 TP2.X U2.5 | length 34
  TOP w0.127: v1(16.99,3.227) 17.03,3.227 17.654,3.851 18.988,3.851 19.062,3.777 19.062,3.354 19.519,2.897 19.766,2.897 20.343,3.474 v1(21.751,3.474) ; J3.4 27.805,4.23 28.121,3.914 28.121,3.734 28.324,3.531 28.89,3.531 v1(28.939,3.579) ; v1(32.571,3.451) 32.571,3.491 32.741,3.662 32.741,6.275 32.816,6.35 33.354,6.35 v1(33.39,6.314)
  SIG w0.127: v1(14.318,0.71) 14.318,0.763 14.158,0.923 14.158,1.482 15.485,2.809 16.572,2.809 v1(16.99,3.227)
  BOTTOM w0.127: TP2.X 13.226,1.69 13.864,1.052 13.864,1.034 14.14,0.758 14.27,0.758 v1(14.318,0.71) ; J2.5 21.554,4 21.751,3.803 v1(21.751,3.474) 21.804,3.422 21.969,3.422 22.52,2.871 23.833,2.871 23.922,2.959 24.411,2.959 25.025,2.345 25.732,2.345 25.929,2.148 26.253,2.148 26.481,2.377 26.481,2.613 26.626,2.758 26.626,3.273 26.834,3.481 28.767,3.481 28.812,3.526 v1@28.939,3.526 ; v1(28.939,3.579) 28.939,3.574 28.962,3.55 28.986,3.526 28.99,3.522 28.994,3.526 29.145,3.526 29.149,3.522 32.358,3.522 32.376,3.504 32.518,3.504 v1(32.571,3.451)
  BOTTOM w0.15: U2.5 32.961,6.314 v1(33.39,6.314)
USB_D_1_N: J1.A7 J1.B7 R4.2 TP1.X Z1.2 | length 7
  TOP w0.18: J1.B7 4.67,5.7 4.553,5.583 4.553,5.017 4.67,4.9 J1.A7 6.076,4.9 6.36,5.184 6.664,5.184 6.74,5.108 7.19,5.108 Z1.2@7.3,4.998 ; Z1.2@7.3,4.87 7.3,4.92 Z1.2@7.3,4.998 ; R4.2 8.564,5.156 7.981,5.156 v1(7.971,5.165) 7.942,5.136 7.41,5.136 7.3,5.026 Z1.2@7.3,4.998
  BOTTOM w0.2: v1@8.091,5.136 8.091,5.028 8.241,4.878 8.241,4.233 TP1.X
USB_D_1_P: J1.A6 J1.B6 R5.2 TP3.X Z2.2 | length 5.7
  TOP w0.18: J1.B6 6.036,5.3 6.153,5.417 6.153,5.562 ; J1.A6 6.036,6.1 6.153,5.983 6.153,5.562 ; R5.2 8.564,5.844 8.079,5.844 8.031,5.892 7.439,5.892 7.429,5.882 6.802,5.882 6.481,5.562 6.153,5.562
  BOTTOM w0.2: v1@8.091,5.863 8.091,5.972 8.241,6.121 8.241,6.767 TP3.X
  other v1: 7.971,5.892
USB_SHIELD_1: C1.2 J1.SHIELD1 R1.2 | length 4.1
  TOP w0.4: J1.SHIELD1 5.162,10.269 6.261,10.269 6.347,10.355 7.55,10.355 8.357,10.355 8.708,10.004 C1.2
VTARGET: C7.2 DL3.A J2.10 J3.1 J4.1 R16.2 U2.6 Z4.2 | length 52
  TOP w0.2: v1@29.314,5.417 29.433,5.536 29.433,5.974 29.566,6.107 31.728,6.107 32.147,6.527 32.147,6.779 32.746,7.377 33.914,7.377 34.495,6.796 34.495,5.971 v1(34.5,5.966) ; 29.408,4.595 29.415,4.588 29.415,3.105
  TOP w0.25: v1(29.314,5.363) 29.314,4.695 29.408,4.602 29.408,4.595 ; 29.415,3.105 29.56,2.96 J3.1 30.675,2.867 J3.1@30.513,2.705
  TOP w0.3: v1(11.718,8.61) 11.775,8.667 11.775,8.881 13.277,10.383 17.151,10.383 17.666,9.867 18.665,9.867 18.84,9.693 v1(19.428,9.693) ; DL3.A 22.509,2.071 J4.1@23.38,1.2 ; v1(30.253,2.047) 30.513,2.308 J3.1@30.513,2.705
  TOP w0.4: v1(19.118,8.003) 19.17,7.95 19.17,5.728 20.026,4.872 20.026,3.737 v1(19.629,3.34)
  SIG w0.4: v1(19.118,8.003) 19.118,9.383 v1(19.428,9.693) ; J4.1 23.934,0.5 29.529,0.5 30.253,1.224 v1(30.253,2.047)
  BOTTOM w0.15: U2.6 33.659,5.7 33.888,5.929 34.463,5.929 v1(34.5,5.966)
  BOTTOM w0.2: v1(29.314,5.363) 29.369,5.363 29.528,5.204 29.767,5.204 R16.2
  BOTTOM w0.4: v1(11.718,8.61) 11.718,8.319 12.102,7.936 13.318,7.936 14.229,7.936 14.463,8.17 14.463,8.974 14.697,9.208 15.164,9.208 15.614,9.658 J2.10
  BOTTOM w0.5: v1(19.629,3.34) 19.667,3.302 19.667,2.994 19.888,2.773 21.03,2.773 22.373,1.43 23.004,1.43 J4.1
pads on no net: Fiducial_3.1 Fiducial_4.1 J1.A8 J1.B8 J1.FIXING J1.SHIELD2 J1.SHIELD3 J1.SHIELD4 J2.6 J2.HOLE J3.7

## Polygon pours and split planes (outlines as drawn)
GND on GND "NONET_L-01_P-001" (solid, remove dead copper, pour order 2): 0,11 0,0 35,0 35,11
+3V3 on SIG "NONET_L-01_P-001" (solid, remove dead copper, pour order 3): 0,11 0,0 35,0 35,11
GND on BOTTOM "NONET_L-01_P-001" (solid, remove dead copper, pour order 1): 0,11 0,0 35,0 35,11
GND on TOP "NONET_L-01_P-001" (solid, remove dead copper, pour order 0): 0,11 0,0 35,0 35,11

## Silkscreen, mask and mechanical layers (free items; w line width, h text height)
Bottom Overlay:
  rectangle: 18.98,8.94 19.38,10.7
  region: 17.328,10.7 16.928,10.7 16.928,8.94 17.328,8.94
  region: 24.948,10.7 24.548,10.7 24.548,8.94 24.948,8.94
Route Tool Path:
  lines w2: -1,0.5 -1,0 ; -1,10.5 -1,11 ; 36,0.5 36,0 ; 36,1 36,0 ; 36,10.5 36,11 ; -1,0 ccw(c0,0) 0,-1 ; -1,0 ccw(c0,0) 0,-1 ; -1,11 cw(c0,11) 0,12 ; -1,11 cw(c0,11) 0,12 ; 0,-1 35,-1 ; 0,12 35,12 ; 35,-1 ccw(c35,0) 36,0 ; 35,-1 ccw(c35,0) 36,0 ; 35,12 cw(c35,11) 36,11 ; 35,12 cw(c35,11) 36,11
Board:
  the board outline again, w0.2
